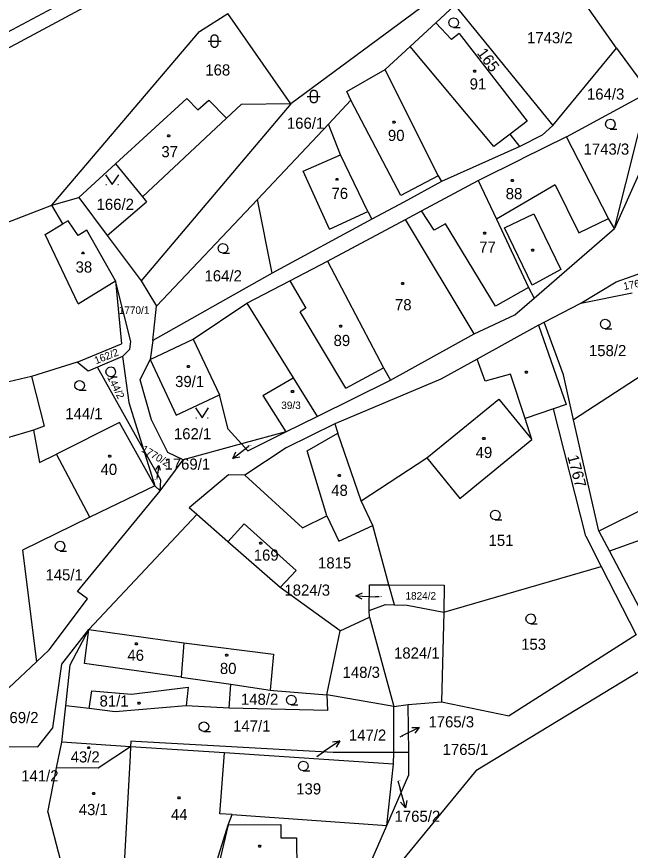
# Model space of a CAD drawing. Extents: x -799786 to -795190, y -1021716 to -1017834.
# Drawn here: x -797729.6 to -797636.1, y -1018913.6 to -1018786.5 of the extents above; entities that cross this region are included whole.
import ezdxf

# ---------------------------------------------------------------- set-up
doc = ezdxf.new("R2010")
doc.units = 0
for name, color, linetype in [('Default', 7, 'Continuous'), ('KN_HRANICE', 7, 'Continuous'), ('KN_KULTURY', 7, 'Continuous'), ('KN_PARCELY', 7, 'Continuous'), ('KN_SLUCKY', 7, 'Continuous')]:
    doc.layers.add(name, color=color, linetype=linetype)

# ---------------------------------------------------------------- blocks, each defined once
blk = doc.blocks.new('304')
at = {"layer": 'Default'}
blk.add_lwpolyline([(0, 0), (-0.38, 0.1), (-0.65, 0.37), (-0.75, 0.74), (-0.65, 1.11), (-0.38, 1.38), (-0.01, 1.48), (0.36, 1.38), (0.63, 1.11), (0.73, 0.73), (0.63, 0.35), (0.36, 0.08), (-0.02, -0.02), (0.98, -0.02)], dxfattribs=at)
blk = doc.blocks.new('314')
at = {"layer": 'Default'}
for p, q in [((-0.95, 0), (-0.85, 0)), ((0.85, 0), (0.95, 0))]:
    blk.add_line(p, q, dxfattribs=at)
blk.add_lwpolyline([(-1, 1.5), (0, 0), (1, 1.5)], dxfattribs=at)
blk = doc.blocks.new('316')
at = {"layer": 'Default'}
for points in [[(-0.5, 1.5), (-0.4, 1.79), (-0.15, 1.97), (0.16, 1.97), (0.41, 1.79), (0.51, 1.5), (0.51, 0.5), (0.41, 0.21), (0.16, 0.03), (-0.15, 0.03), (-0.4, 0.21), (-0.5, 0.5), (-0.5, 1.5)], [(-1, 1), (0.27, 1), (1, 1)]]:
    blk.add_lwpolyline(points, dxfattribs=at)
blk = doc.blocks.new('NAHRADNI_SYMBOL')
at = {"layer": 'Default'}
blk.add_lwpolyline([(0.09, 0.15), (0.18, 0), (0.09, -0.15), (-0.09, -0.15), (-0.18, 0), (-0.09, 0.15), (0.09, 0.15)], dxfattribs=at)
blk = doc.blocks.new('10292')
at = {"layer": 'Default'}
blk.add_line((0, 3), (0, 0), dxfattribs=at)
blk.add_lwpolyline([(-0.5, 2), (0, 3), (0.5, 2)], dxfattribs=at)
blk = doc.blocks.new('402')
at = {"layer": 'Default'}
blk.add_lwpolyline([(0.09, 0.15), (0.18, 0), (0.09, -0.15), (-0.09, -0.15), (-0.18, 0), (-0.09, 0.15), (0.09, 0.15)], dxfattribs=at)

msp = doc.modelspace()

# ---------------------------------------------------------------- linework, layer by layer
at = {"layer": 'KN_HRANICE'}
for p, q in [((-797748.74, -1018798.28), (-797675.47, -1018759.21)), ((-797747.91, -1018800.44), (-797673.64, -1018760.45)), ((-797643.54, -1018766.95), (-797687.85, -1018799.78)), ((-797638.22, -1018791.29), (-797650.64, -1018773.5)), ((-797665.74, -1018787.43), (-797662.83, -1018784.74)), ((-797662.83, -1018784.74), (-797647.92, -1018803.09)), ((-797701.76, -1018788.72), (-797697.43, -1018786)), ((-797687.85, -1018799.78), (-797697.43, -1018786)), ((-797669.66, -1018791.04), (-797665.74, -1018787.43)), ((-797663.36, -1018789.94), (-797665.74, -1018787.43)), ((-797724.22, -1018815.22), (-797701.76, -1018788.72)), ((-797662.18, -1018789.03), (-797663.36, -1018789.94)), ((-797662.18, -1018789.03), (-797651.84, -1018802.41)), ((-797673.44, -1018794.53), (-797669.66, -1018791.04)), ((-797647.92, -1018803.09), (-797638.22, -1018791.29)), ((-797638.22, -1018791.29), (-797633.31, -1018798)), ((-797679.32, -1018797.89), (-797673.44, -1018794.53)), ((-797665.4, -1018810.74), (-797673.44, -1018794.53)), ((-797678.67, -1018799.2), (-797679.32, -1018797.89)), ((-797714.55, -1018808.94), (-797703.68, -1018798.94)), ((-797703.68, -1018798.94), (-797702, -1018800.68)), ((-797702, -1018800.68), (-797700.32, -1018799.19)), ((-797700.32, -1018799.19), (-797697.61, -1018801.94)), ((-797682.11, -1018802.85), (-797678.67, -1018799.2)), ((-797645.82, -1018804.79), (-797633.31, -1018798)), ((-797638.53, -1018818.79), (-797633.31, -1018798)), ((-797687.85, -1018799.78), (-797710.63, -1018826.78)), ((-797695.4, -1018799.87), (-797697.61, -1018801.94)), ((-797687.85, -1018799.78), (-797695.4, -1018799.87)), ((-797692.93, -1018814.33), (-797682.11, -1018802.85)), ((-797680.27, -1018807.55), (-797682.11, -1018802.85)), ((-797651.84, -1018802.41), (-797654.42, -1018804.38)), ((-797631.1, -1018802.05), (-797638.53, -1018818.79)), ((-797647.92, -1018803.09), (-797649.55, -1018804.54)), ((-797652.97, -1018806.25), (-797654.42, -1018804.38)), ((-797649.55, -1018804.54), (-797652.97, -1018806.25)), ((-797645.82, -1018804.79), (-797652.64, -1018808.15)), ((-797639.45, -1018817.24), (-797645.82, -1018804.79)), ((-797652.97, -1018806.25), (-797664.86, -1018811.61)), ((-797676.12, -1018816.19), (-797680.27, -1018807.55)), ((-797659.29, -1018811.44), (-797652.64, -1018808.15)), ((-797720.12, -1018814.07), (-797714.55, -1018808.94)), ((-797714.55, -1018808.94), (-797710.44, -1018813.97)), ((-797664.86, -1018811.61), (-797670.64, -1018814.74)), ((-797667.93, -1018816.07), (-797659.29, -1018811.44)), ((-797665.4, -1018810.74), (-797664.86, -1018811.61)), ((-797659.29, -1018811.44), (-797656.51, -1018817.35)), ((-797724.22, -1018815.22), (-797720.12, -1018814.07)), ((-797720.12, -1018814.07), (-797715.81, -1018819.84)), ((-797710.44, -1018813.97), (-797709.82, -1018814.72)), ((-797708.29, -1018830.62), (-797692.93, -1018814.33)), ((-797690.68, -1018825.6), (-797692.93, -1018814.33)), ((-797735.14, -1018819.43), (-797724.22, -1018815.22)), ((-797722.54, -1018818.09), (-797724.22, -1018815.22)), ((-797715.81, -1018819.84), (-797709.82, -1018814.72)), ((-797670.64, -1018814.74), (-797675.49, -1018817.37)), ((-797676.12, -1018816.19), (-797675.49, -1018817.37)), ((-797670.38, -1018817.38), (-797667.93, -1018816.07)), ((-797721.73, -1018817.59), (-797722.54, -1018818.09)), ((-797720.24, -1018819.83), (-797721.73, -1018817.59)), ((-797675.49, -1018817.37), (-797690.68, -1018825.6)), ((-797682.25, -1018823.74), (-797670.38, -1018817.38)), ((-797659.88, -1018834.86), (-797670.38, -1018817.38)), ((-797656.51, -1018817.35), (-797651.61, -1018827.76)), ((-797638.53, -1018818.79), (-797639.45, -1018817.24)), ((-797718.93, -1018819.02), (-797720.24, -1018819.83)), ((-797714.53, -1018826.76), (-797718.93, -1018819.02)), ((-797650.78, -1018829.39), (-797638.53, -1018818.79)), ((-797715.81, -1018819.84), (-797710.63, -1018826.78)), ((-797688, -1018826.77), (-797682.25, -1018823.74)), ((-797682.25, -1018823.74), (-797673.71, -1018840.04)), ((-797690.68, -1018825.6), (-797708.84, -1018835.87)), ((-797714.53, -1018826.76), (-797713.63, -1018836.38)), ((-797710.63, -1018826.78), (-797708.29, -1018830.62)), ((-797694.51, -1018830.16), (-797688, -1018826.77)), ((-797651.61, -1018827.76), (-797650.78, -1018829.39)), ((-797653.72, -1018831.93), (-797650.78, -1018829.39)), ((-797643.65, -1018830.18), (-797635.85, -1018828.6)), ((-797708.84, -1018835.87), (-797708.29, -1018830.62)), ((-797702.69, -1018835.65), (-797694.51, -1018830.16)), ((-797694.51, -1018830.16), (-797687.47, -1018841.55)), ((-797649.22, -1018833.06), (-797643.65, -1018830.18)), ((-797659.88, -1018834.86), (-797653.72, -1018831.93)), ((-797650.09, -1018833.51), (-797659.45, -1018838.69)), ((-797650.09, -1018833.51), (-797649.22, -1018833.06)), ((-797650.09, -1018833.51), (-797645.87, -1018845.59)), ((-797646.32, -1018841.1), (-797649.22, -1018833.06)), ((-797709.28, -1018838.75), (-797702.69, -1018835.65)), ((-797708.84, -1018835.87), (-797709.28, -1018838.75)), ((-797672.63, -1018841.92), (-797659.88, -1018834.86)), ((-797720.36, -1018839.14), (-797713.63, -1018836.38)), ((-797713.45, -1018838.27), (-797717.3, -1018839.92)), ((-797713.45, -1018838.27), (-797712.53, -1018845.31)), ((-797630.19, -1018838.4), (-797644.78, -1018847.97)), ((-797720.36, -1018839.14), (-797727.34, -1018841.32)), ((-797718.68, -1018840.51), (-797720.36, -1018839.14)), ((-797717.3, -1018839.92), (-797718.68, -1018840.51)), ((-797710.28, -1018852.49), (-797717.3, -1018839.92)), ((-797710.76, -1018841.83), (-797709.28, -1018838.75)), ((-797709.28, -1018838.75), (-797705.29, -1018847.24)), ((-797659.45, -1018838.69), (-797665, -1018841.76)), ((-797673.71, -1018840.04), (-797672.63, -1018841.92)), ((-797644.78, -1018847.97), (-797646.32, -1018841.1)), ((-797727.34, -1018841.32), (-797735.17, -1018843.2)), ((-797727.34, -1018841.32), (-797725.42, -1018848.9)), ((-797709.08, -1018847.93), (-797710.76, -1018841.83)), ((-797692.08, -1018844.26), (-797687.47, -1018841.55)), ((-797687.47, -1018841.55), (-797683.82, -1018847.45)), ((-797683.82, -1018847.45), (-797672.63, -1018841.92)), ((-797665, -1018841.76), (-797681.12, -1018848.58)), ((-797594, -1018841.5), (-797640.89, -1018864.9)), ((-797705.29, -1018847.24), (-797698.7, -1018844.14)), ((-797697.38, -1018849.37), (-797698.7, -1018844.14)), ((-797692.08, -1018844.26), (-797688.58, -1018849.8)), ((-797712.53, -1018845.31), (-797710.28, -1018852.49)), ((-797647.8, -1018846.26), (-797652.14, -1018847.77)), ((-797645.87, -1018845.59), (-797647.8, -1018846.26)), ((-797642.87, -1018865.69), (-797647.8, -1018846.26)), ((-797688.58, -1018849.8), (-797683.82, -1018847.45)), ((-797713.93, -1018848.33), (-797723.54, -1018853.2)), ((-797708.55, -1018857.99), (-797713.93, -1018848.33)), ((-797706.59, -1018852.92), (-797709.08, -1018847.93)), ((-797681.12, -1018848.58), (-797688.53, -1018852.2)), ((-797681.12, -1018848.58), (-797680.66, -1018849.99)), ((-797651.1, -1018850.96), (-797652.14, -1018847.77)), ((-797640.89, -1018864.9), (-797644.78, -1018847.97)), ((-797725.42, -1018848.9), (-797727.03, -1018849.53)), ((-797727.03, -1018849.53), (-797726.1, -1018854.45)), ((-797695.33, -1018851.63), (-797697.38, -1018849.37)), ((-797688.58, -1018849.8), (-797695.33, -1018851.63)), ((-797694.39, -1018852.67), (-797688.58, -1018849.8)), ((-797677.14, -1018860.31), (-797680.66, -1018849.99)), ((-797662.07, -1018859.93), (-797651.1, -1018850.96)), ((-797710.28, -1018852.49), (-797708.55, -1018857.99)), ((-797695.33, -1018851.63), (-797704.22, -1018854.04)), ((-797694.39, -1018852.67), (-797695.33, -1018851.63)), ((-797688.53, -1018852.2), (-797694.84, -1018856.38)), ((-797726.1, -1018854.45), (-797723.54, -1018853.2)), ((-797704.22, -1018854.04), (-797706.59, -1018852.92)), ((-797677.14, -1018860.31), (-797667.1, -1018853.75)), ((-797667.1, -1018853.75), (-797662.07, -1018859.93)), ((-797707.73, -1018858.79), (-797704.22, -1018854.04)), ((-797697.32, -1018856.32), (-797703.3, -1018861.39)), ((-797694.84, -1018856.38), (-797697.32, -1018856.32)), ((-797694.84, -1018856.38), (-797686.04, -1018864.39)), ((-797720.31, -1018874.12), (-797707.73, -1018858.79)), ((-797708.55, -1018857.99), (-797718.43, -1018862.81)), ((-797708.55, -1018857.99), (-797707.73, -1018858.79)), ((-797702.16, -1018862.39), (-797703.3, -1018861.39)), ((-797675.33, -1018864.07), (-797677.14, -1018860.31)), ((-797718.43, -1018862.81), (-797728.71, -1018867.83)), ((-797718.61, -1018879.92), (-797702.16, -1018862.39)), ((-797697.43, -1018866.54), (-797702.16, -1018862.39)), ((-797686.04, -1018864.39), (-797682.34, -1018862.59)), ((-797682.34, -1018862.59), (-797680.51, -1018866.45)), ((-797694.96, -1018863.78), (-797697.43, -1018866.54)), ((-797687.01, -1018870.94), (-797694.96, -1018863.78)), ((-797680.51, -1018866.45), (-797675.33, -1018864.07)), ((-797672.88, -1018873.12), (-797675.33, -1018864.07)), ((-797640.89, -1018864.9), (-797639.27, -1018867.99)), ((-797689.48, -1018873.52), (-797697.43, -1018866.54)), ((-797642.87, -1018865.69), (-797640.54, -1018870.29)), ((-797634.08, -1018866.08), (-797639.27, -1018867.99)), ((-797728.71, -1018867.83), (-797726.58, -1018884.85)), ((-797639.27, -1018867.99), (-797633.26, -1018879.48)), ((-797664.54, -1018877.26), (-797640.54, -1018870.29)), ((-797640.54, -1018870.29), (-797635.25, -1018880.75)), ((-797689.48, -1018873.52), (-797687.01, -1018870.94)), ((-797718.81, -1018875.24), (-797720.31, -1018874.12)), ((-797680.32, -1018880.14), (-797689.48, -1018873.52)), ((-797675.89, -1018877.04), (-797675.87, -1018873.11)), ((-797675.87, -1018873.11), (-797672.88, -1018873.12)), ((-797672.88, -1018873.12), (-797664.46, -1018873.14)), ((-797672.05, -1018876.16), (-797672.88, -1018873.12)), ((-797664.46, -1018873.14), (-797664.54, -1018877.26)), ((-797724.67, -1018883.03), (-797718.81, -1018875.24)), ((-797675.89, -1018877.04), (-797673.39, -1018876.11)), ((-797673.39, -1018876.11), (-797672.05, -1018876.16)), ((-797672.05, -1018876.16), (-797670.1, -1018876.23)), ((-797670.1, -1018876.23), (-797664.54, -1018877.26)), ((-797680.32, -1018880.14), (-797675.87, -1018878.02)), ((-797675.87, -1018878.02), (-797675.89, -1018877.04)), ((-797675.87, -1018878.02), (-797672.13, -1018891.66)), ((-797664.54, -1018877.26), (-797664.88, -1018890.93)), ((-797722.73, -1018885.2), (-797718.61, -1018879.92)), ((-797721.43, -1018885.29), (-797718.61, -1018879.92)), ((-797718.61, -1018879.92), (-797704.12, -1018881.95)), ((-797682.33, -1018889.89), (-797680.32, -1018880.14)), ((-797635.25, -1018880.75), (-797654.58, -1018893.08)), ((-797726.58, -1018884.85), (-797724.67, -1018883.03)), ((-797704.12, -1018881.95), (-797704.52, -1018887.17)), ((-797630.91, -1018883.96), (-797659.63, -1018901.44)), ((-797730.77, -1018888.83), (-797726.58, -1018884.85)), ((-797724.07, -1018894.93), (-797722.73, -1018885.2)), ((-797722.12, -1018891.54), (-797721.43, -1018885.29)), ((-797704.52, -1018887.17), (-797696.99, -1018888.27)), ((-797718.55, -1018891.97), (-797718.15, -1018889.28)), ((-797718.15, -1018889.28), (-797712.12, -1018889.76)), ((-797712.12, -1018889.76), (-797703.45, -1018888.7)), ((-797703.45, -1018888.7), (-797703.77, -1018891.55)), ((-797697.24, -1018891.9), (-797696.99, -1018888.27)), ((-797696.99, -1018888.27), (-797690.97, -1018889.15)), ((-797690.97, -1018889.15), (-797690.45, -1018889.23)), ((-797690.45, -1018889.23), (-797682.33, -1018889.89)), ((-797682.33, -1018889.89), (-797682.23, -1018892.25)), ((-797672.13, -1018891.66), (-797682.33, -1018889.89)), ((-797722.74, -1018897.08), (-797722.12, -1018891.54)), ((-797718.55, -1018891.97), (-797722.12, -1018891.54)), ((-797714.61, -1018892.45), (-797718.55, -1018891.97)), ((-797703.77, -1018891.55), (-797714.61, -1018892.45)), ((-797697.24, -1018891.9), (-797703.77, -1018891.55)), ((-797682.23, -1018892.25), (-797697.24, -1018891.9)), ((-797672.13, -1018891.66), (-797669.95, -1018891.33)), ((-797672.12, -1018898.65), (-797672.13, -1018891.66)), ((-797669.95, -1018891.33), (-797664.88, -1018890.93)), ((-797669.88, -1018898.65), (-797669.95, -1018891.33)), ((-797664.88, -1018890.93), (-797654.58, -1018893.08)), ((-797726.37, -1018897.8), (-797724.07, -1018894.93)), ((-797723.51, -1018901), (-797722.74, -1018897.08)), ((-797712.25, -1018897.78), (-797722.74, -1018897.08)), ((-797712.21, -1018896.96), (-797712.25, -1018897.78)), ((-797711.5, -1018897), (-797712.21, -1018896.96)), ((-797681.37, -1018898.66), (-797711.5, -1018897)), ((-797731.32, -1018897.77), (-797726.37, -1018897.8)), ((-797712.25, -1018897.78), (-797717.17, -1018901.04)), ((-797712.25, -1018897.78), (-797712.31, -1018899.12)), ((-797697.92, -1018898.73), (-797712.25, -1018897.78)), ((-797712.31, -1018899.12), (-797713.28, -1018916.65)), ((-797698.65, -1018908.02), (-797697.92, -1018898.73)), ((-797672.2, -1018900.44), (-797697.92, -1018898.73)), ((-797672.12, -1018898.65), (-797681.37, -1018898.66)), ((-797672.2, -1018900.44), (-797672.12, -1018898.65)), ((-797669.88, -1018898.65), (-797672.12, -1018898.65)), ((-797669.87, -1018902.07), (-797669.88, -1018898.65)), ((-797673.23, -1018909.82), (-797672.2, -1018900.44)), ((-797724.84, -1018907.79), (-797723.51, -1018901)), ((-797717.17, -1018901.04), (-797723.51, -1018901)), ((-797673.23, -1018909.82), (-797669.87, -1018902.07)), ((-797659.63, -1018901.44), (-797672.91, -1018917.57)), ((-797724.84, -1018907.79), (-797722.95, -1018914.98)), ((-797696.79, -1018908.13), (-797698.65, -1018908.02)), ((-797697.37, -1018909.72), (-797696.79, -1018908.13)), ((-797696.79, -1018908.13), (-797673.23, -1018909.82)), ((-797700.01, -1018918.03), (-797697.37, -1018909.72)), ((-797677.48, -1018919.62), (-797673.23, -1018909.82))]:
    msp.add_line(p, q, dxfattribs=at)
for points in [[(-797643.65, -1018830.18), (-797638.25, -1018826.91), (-797631.8, -1018824.6), (-797630.32, -1018824.47)], [(-797713.45, -1018838.27), (-797712.36, -1018837.17), (-797712.19, -1018836.02), (-797714.53, -1018826.76)], [(-797707.73, -1018858.79), (-797707.66, -1018857.17), (-797710.28, -1018852.49)]]:
    msp.add_lwpolyline(points, dxfattribs=at)
at = {"layer": 'KN_PARCELY'}
for p, q in [((-797694.2, -1018851.92), (-797694.32, -1018852.01)), ((-797674.37, -1018874.94), (-797674.94, -1018874.91)), ((-797671.17, -1018896.29), (-797670.95, -1018896.18)), ((-797683.89, -1018899.28), (-797682.85, -1018898.57)), ((-797671.52, -1018902.97), (-797671.18, -1018904.2))]:
    msp.add_line(p, q, dxfattribs=at)
at = {"layer": 'KN_SLUCKY'}
for p, q in [((-797656.92, -1018806.29), (-797669.66, -1018791.04)), ((-797671.09, -1018813.75), (-797678.67, -1018799.2)), ((-797697.61, -1018801.94), (-797710.44, -1018813.97)), ((-797654.42, -1018804.38), (-797656.92, -1018806.29)), ((-797685.96, -1018810.05), (-797680.27, -1018807.55)), ((-797681.94, -1018818.9), (-797685.96, -1018810.05)), ((-797665.4, -1018810.74), (-797671.09, -1018813.75)), ((-797647.57, -1018812.13), (-797656.51, -1018817.35)), ((-797647.57, -1018812.13), (-797643.98, -1018819.45)), ((-797681.94, -1018818.9), (-797676.12, -1018816.19)), ((-797665.99, -1018819.05), (-797667.93, -1018816.07)), ((-797725.28, -1018819.7), (-797722.54, -1018818.09)), ((-797664.25, -1018818.05), (-797665.99, -1018819.05)), ((-797656.65, -1018830.63), (-797664.25, -1018818.05)), ((-797643.98, -1018819.45), (-797639.45, -1018817.24)), ((-797720.22, -1018830.24), (-797725.28, -1018819.7)), ((-797720.22, -1018830.24), (-797714.53, -1018826.76)), ((-797688, -1018826.77), (-797685.55, -1018830.93)), ((-797651.61, -1018827.76), (-797656.65, -1018830.63)), ((-797685.55, -1018830.93), (-797686.42, -1018831.49)), ((-797679.44, -1018843.1), (-797686.42, -1018831.49)), ((-797702.69, -1018835.65), (-797698.7, -1018844.14)), ((-797658.23, -1018842.03), (-797659.45, -1018838.69)), ((-797679.44, -1018843.1), (-797673.71, -1018840.04)), ((-797654.37, -1018840.97), (-797658.23, -1018842.03)), ((-797652.14, -1018847.77), (-797654.37, -1018840.97)), ((-797667.1, -1018853.75), (-797656.13, -1018844.78)), ((-797656.13, -1018844.78), (-797651.1, -1018850.96)), ((-797727.03, -1018849.53), (-797735.63, -1018852.02)), ((-797685.34, -1018852.69), (-797680.66, -1018849.99)), ((-797718.43, -1018862.81), (-797723.54, -1018853.2)), ((-797682.34, -1018862.59), (-797685.34, -1018852.69)), ((-797719.25, -1018885.11), (-797718.61, -1018879.92)), ((-797704.12, -1018881.95), (-797690.45, -1018883.67)), ((-797690.45, -1018883.67), (-797690.97, -1018889.15)), ((-797704.52, -1018887.17), (-797719.25, -1018885.11)), ((-797697.37, -1018909.72), (-797699.02, -1018916.69)), ((-797697.37, -1018909.72), (-797689.37, -1018909.63)), ((-797689.37, -1018909.63), (-797689.36, -1018911.67)), ((-797689.36, -1018911.67), (-797686.97, -1018911.69)), ((-797686.97, -1018911.69), (-797686.94, -1018916.61))]:
    msp.add_line(p, q, dxfattribs=at)
msp.add_lwpolyline([(-797655.29, -1018818.66), (-797650.83, -1018816.52), (-797646.71, -1018825.04), (-797651.09, -1018827.41)], close=True, dxfattribs=at)

# ---------------------------------------------------------------- block references
at = {"layer": 'KN_KULTURY'}
for name, p in [('304', (-797663.02, -1018788.12)), ('316', (-797699.45, -1018791.21)), ('402', (-797659.83, -1018794.77)), ('316', (-797684.34, -1018799.65)), ('402', (-797672.1, -1018802.56)), ('304', (-797639.15, -1018803.6)), ('402', (-797706.42, -1018804.67)), ('314', (-797715.05, -1018812.09)), ('402', (-797680.81, -1018811.28)), ('402', (-797654.09, -1018811.45)), ('402', (-797658.31, -1018819.47)), ('304', (-797698.16, -1018822.54)), ('402', (-797651, -1018822.07)), ('402', (-797719.49, -1018822.51)), ('NAHRADNI_SYMBOL', (-797670.79, -1018827.14)), ('402', (-797680.23, -1018833.67)), ('304', (-797639.93, -1018834.07)), ('304', (-797715.25, -1018841.37)), ('402', (-797703.45, -1018839.83)), ('402', (-797651.95, -1018840.66)), ('304', (-797720.01, -1018843.43)), ('NAHRADNI_SYMBOL', (-797687.58, -1018843.62)), ('314', (-797701.36, -1018847.64)), ('402', (-797658.43, -1018850.81)), ('402', (-797715.41, -1018853.47)), ('402', (-797680.46, -1018856.44)), ('304', (-797656.68, -1018863.2)), ('304', (-797722.97, -1018867.94)), ('402', (-797692.41, -1018866.75)), ('304', (-797651.27, -1018879.03)), ('402', (-797711.36, -1018882.09)), ('402', (-797697.59, -1018883.83)), ('304', (-797687.75, -1018891.4)), ('NAHRADNI_SYMBOL', (-797710.94, -1018891.16)), ('304', (-797701.07, -1018895.46)), ('402', (-797718.62, -1018897.93)), ('304', (-797685.92, -1018901.46)), ('402', (-797717.87, -1018904.91)), ('NAHRADNI_SYMBOL', (-797704.86, -1018905.6)), ('402', (-797692.58, -1018912.94))]:
    msp.add_blockref(name, p, dxfattribs=at)
at = {"layer": 'KN_PARCELY'}
for p, rotation in [((-797694.32, -1018852.01), 127.76958799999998), ((-797674.94, -1018874.91), 87.089585), ((-797670.95, -1018896.18), -63.49434100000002), ((-797682.85, -1018898.57), -55.53022799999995), ((-797671.18, -1018904.2), -164.39220900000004)]:
    msp.add_blockref('10292', p, dxfattribs=dict(at, rotation=rotation))
at = {"layer": 'KN_PARCELY', "xscale": 0.67, "yscale": 0.67, "rotation": -7.860138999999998}
msp.add_blockref('10292', (-797708.23, -1018856.91), dxfattribs=at)

# ---------------------------------------------------------------- texts
at = {"layer": 'KN_PARCELY'}
for s, height, p in [('1743/2', 1.7, (-797651.85, -1018790.54)), ('168', 1.7, (-797700.86, -1018795.45)), ('91', 1.7, (-797660.59, -1018797.58)), ('164/3', 1.7, (-797642.72, -1018799.13)), ('166/1', 1.7, (-797688.43, -1018803.57)), ('90', 1.7, (-797673.04, -1018805.43)), ('37', 1.7, (-797707.55, -1018807.91)), ('1743/3', 1.7, (-797643.24, -1018807.52)), ('76', 1.7, (-797681.64, -1018814.27)), ('88', 1.7, (-797655.1, -1018814.31)), ('166/2', 1.7, (-797717.42, -1018815.94)), ('77', 1.7, (-797659.14, -1018822.47)), ('38', 1.7, (-797720.62, -1018825.5)), ('164/2', 1.7, (-797700.98, -1018826.84)), ('78', 1.7, (-797671.97, -1018831.25)), ('89', 1.7, (-797681.32, -1018836.7)), ('158/2', 1.7, (-797642.42, -1018838.24)), ('39/1', 1.7, (-797705.46, -1018842.95)), ('144/1', 1.7, (-797722.19, -1018847.86)), ('39/3', 1.14, (-797689.29, -1018846.3)), ('162/1', 1.7, (-797705.64, -1018850.92)), ('1769/1', 0.1, (-797694.18, -1018851.92)), ('49', 1.7, (-797659.68, -1018853.77)), ('1769/1', 1.7, (-797707.08, -1018855.55)), ('40', 1.7, (-797716.82, -1018856.35)), ('1770/2', 0.1, (-797708.59, -1018857.14)), ('48', 1.7, (-797681.68, -1018859.54)), ('151', 1.7, (-797657.71, -1018867.18)), ('169', 1.7, (-797693.48, -1018869.42)), ('1815', 1.7, (-797683.69, -1018870.61)), ('145/1', 1.7, (-797725.21, -1018872.43)), ('1824/3', 1.7, (-797688.81, -1018874.76)), ('1824/2', 1.14, (-797670.37, -1018875.35)), ('1824/3', 0.1, (-797674.35, -1018874.94)), ('153', 1.7, (-797652.75, -1018883.01)), ('46', 1.7, (-797712.73, -1018884.69)), ('1824/1', 1.7, (-797672.11, -1018884.36)), ('80', 1.7, (-797698.64, -1018886.7)), ('148/3', 1.7, (-797679.95, -1018887.29)), ('81/1', 1.7, (-797716.97, -1018891.66)), ('148/2', 1.7, (-797695.43, -1018891.4)), ('1769/2', 1.7, (-797733.22, -1018894.19)), ('1765/3', 1.7, (-797666.87, -1018894.84)), ('147/1', 1.7, (-797696.63, -1018895.49)), ('147/2', 1.7, (-797678.99, -1018896.87)), ('1765/3', 0.1, (-797671.15, -1018896.29)), ('43/2', 1.7, (-797721.37, -1018900.19)), ('1765/1', 1.7, (-797664.71, -1018899.05)), ('147/2', 0.1, (-797683.87, -1018899.28)), ('141/2', 1.7, (-797728.91, -1018903.08)), ('139', 1.7, (-797687.01, -1018905.06)), ('1765/2', 0.1, (-797671.5, -1018902.97)), ('43/1', 1.7, (-797720.14, -1018908.22)), ('44', 1.7, (-797706.09, -1018908.97)), ('1765/2', 1.7, (-797672.03, -1018909.24))]:
    msp.add_text(s, height=height, dxfattribs=at).set_placement(p)
for s, height, rotation, p in [('165', 1.7, 306.59, (-797659.56, -1018792.04)), ('1769/4', 1.14, 11.287, (-797637.06, -1018828.16)), ('1770/1', 1.14, 0.344, (-797714.04, -1018831.81)), ('162/2', 1.14, 21.601, (-797717.5, -1018839.48)), ('144/2', 1.14, 296.62, (-797715.83, -1018841.47)), ('1770/2', 1.14, 328.878, (-797710.71, -1018852.72)), ('1767', 1.7, 284.817, (-797645.72, -1018853.54))]:
    msp.add_text(s, height=height, rotation=rotation, dxfattribs=at).set_placement(p)

doc.saveas('drawing.dxf')
